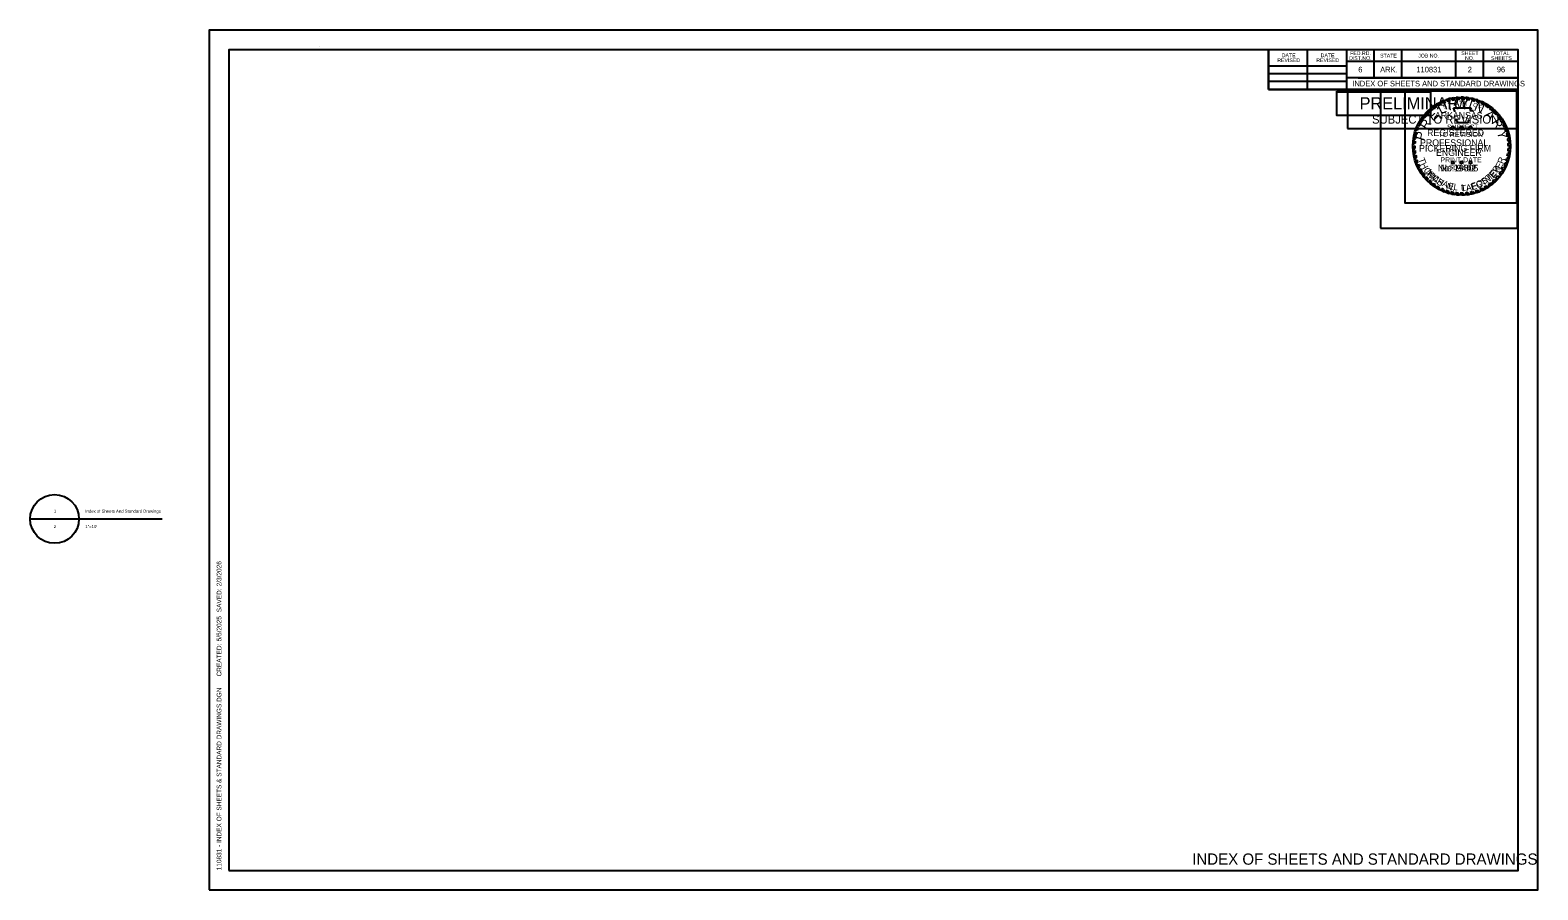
# Model space of a CAD drawing. Extents: x -0.19 to 1.42, y 0 to 0.92.
import ezdxf

# ---------------------------------------------------------------- set-up
doc = ezdxf.new("R2010")
doc.units = 0
for name, color, linetype in [('Default', 7, 'Continuous'), ('DSN_DRFT_Guideline-No-Plot', 7, 'Continuous'), ('SHET_Annotations', 7, 'Continuous'), ('SHET_Border-Lines', 7, 'Continuous'), ('SHET_Border-Text', 7, 'Continuous'), ('SHET_Stamp-Prelim', 7, 'Continuous'), ('SHET_Stamp-Seal', 7, 'Continuous'), ('STAMP_PE DIG SIG', 7, 'Continuous'), ('STAMP_PE_BACKGROUND', 7, 'Continuous'), ('STAMP_PE_FOSTER', 7, 'Continuous'), ('STAMP_PE_SEAL-INFO', 7, 'Continuous'), ('STAMP_PE_TAEGTMEYER', 7, 'Continuous'), ('STAMP_PRELIMINARY', 7, 'Continuous')]:
    doc.layers.add(name, color=color, linetype=linetype)

msp = doc.modelspace()

# ---------------------------------------------------------------- linework, layer by layer
at = {"layer": 'Default'}
for p, q in [((-0.191, 0.3955), (-0.1389, 0.3955)), ((-0.1647, 0.3955), (-0.0504, 0.3955))]:
    msp.add_line(p, q, dxfattribs=at)
msp.add_circle((-0.165, 0.3955), 0.026, dxfattribs=at)
at = {"layer": 'DSN_DRFT_Guideline-No-Plot'}
msp.add_lwpolyline([(0, 0), (1.4167, 0), (1.4167, 0.9167), (0, 0.9167)], close=True, dxfattribs=at)
at = {"layer": 'SHET_Border-Lines'}
for p, q in [((0.1176, 0.8988), (0.1176, 0.8988)), ((0.1176, 0.8988), (0.1176, 0.8988)), ((1.1296, 0.8534), (1.1296, 0.8958)), ((1.1711, 0.8534), (1.1711, 0.8958)), ((1.2127, 0.8958), (1.2127, 0.8534)), ((1.2417, 0.8958), (1.2417, 0.866)), ((1.2712, 0.8958), (1.2712, 0.866)), ((1.3289, 0.8958), (1.3289, 0.866)), ((1.3584, 0.8958), (1.3584, 0.866)), ((1.1296, 0.8786), (1.2127, 0.8786)), ((1.1296, 0.8706), (1.2127, 0.8706)), ((1.3958, 0.8832), (1.2127, 0.8832)), ((1.3958, 0.8833), (1.3958, 0.8833)), ((1.1296, 0.8622), (1.2127, 0.8622)), ((1.3958, 0.8534), (1.1296, 0.8534)), ((1.3958, 0.866), (1.2127, 0.866)), ((1.2252, 0.866), (1.3958, 0.866))]:
    msp.add_line(p, q, dxfattribs=at)
for points in [[(0.0208, 0.0208), (1.3958, 0.0208), (1.3958, 0.8958), (0.0208, 0.8958)], [(1.1296, 0.8534), (1.3958, 0.8534), (1.3958, 0.8958), (1.1296, 0.8958)]]:
    msp.add_lwpolyline(points, close=True, dxfattribs=at)
at = {"layer": 'SHET_Stamp-Prelim'}
msp.add_lwpolyline([(1.2137, 0.8119), (1.3948, 0.8119), (1.3948, 0.8524), (1.2137, 0.8524)], close=True, dxfattribs=at)
at = {"layer": 'SHET_Stamp-Seal'}
msp.add_line((1.3219, 0.7895), (1.3219, 0.7895), dxfattribs=at)
msp.add_lwpolyline([(1.249, 0.7057), (1.3948, 0.7057), (1.3948, 0.8524), (1.249, 0.8524)], close=True, dxfattribs=at)
at = {"layer": 'STAMP_PE DIG SIG'}
msp.add_lwpolyline([(1.2022, 0.8508), (1.3022, 0.8508), (1.3022, 0.8258), (1.2022, 0.8258)], close=True, dxfattribs=at)
at = {"layer": 'STAMP_PE_BACKGROUND'}
for points in [[(1.2022, 0.8517), (1.3022, 0.8517), (1.3022, 0.8258), (1.2022, 0.8258)], [(1.3942, 0.8517), (1.275, 0.8517), (1.275, 0.7325), (1.3942, 0.7325)]]:
    msp.add_lwpolyline(points, close=True, dxfattribs=at)
at = {"layer": 'STAMP_PE_SEAL-INFO'}
for p, q in [((1.3066, 0.8363), (1.309, 0.8352)), ((1.3087, 0.8377), (1.3112, 0.8365)), ((1.3112, 0.8391), (1.3138, 0.8378)), ((1.3137, 0.8403), (1.3158, 0.8387)), ((1.3165, 0.8415), (1.3181, 0.8397)), ((1.3184, 0.8422), (1.3206, 0.8405)), ((1.3217, 0.8432), (1.3233, 0.8413)), ((1.3239, 0.8438), (1.3259, 0.8418)), ((1.3266, 0.8443), (1.3283, 0.8422)), ((1.3295, 0.8447), (1.331, 0.8426)), ((1.3336, 0.8427), (1.3318, 0.8449)), ((1.3364, 0.8428), (1.3348, 0.845)), ((1.3389, 0.8426), (1.3375, 0.845)), ((1.3417, 0.8424), (1.3401, 0.8448)), ((1.3441, 0.842), (1.3427, 0.8445)), ((1.3473, 0.8413), (1.3463, 0.8439)), ((1.3495, 0.8407), (1.3486, 0.8433)), ((1.352, 0.8399), (1.3512, 0.8426)), ((1.3544, 0.839), (1.3536, 0.8418)), ((1.357, 0.8379), (1.3564, 0.8406)), ((1.3594, 0.8366), (1.359, 0.8394)), ((1.3616, 0.8353), (1.3614, 0.8381)), ((1.364, 0.8337), (1.3639, 0.8366)), ((1.2917, 0.8213), (1.2946, 0.8215)), ((1.293, 0.8232), (1.2959, 0.8232)), ((1.2946, 0.8253), (1.2977, 0.8254)), ((1.2965, 0.8276), (1.2994, 0.8274)), ((1.2983, 0.8295), (1.3014, 0.8293)), ((1.3002, 0.8313), (1.3028, 0.8306)), ((1.3021, 0.833), (1.3051, 0.8325)), ((1.3042, 0.8348), (1.3068, 0.8337)), ((1.3269, 0.8337), (1.3456, 0.8337)), ((1.3276, 0.832), (1.3269, 0.8337)), ((1.3281, 0.8303), (1.3276, 0.832)), ((1.3282, 0.8297), (1.3281, 0.8303)), ((1.3293, 0.8201), (1.3291, 0.8213)), ((1.331, 0.8201), (1.3293, 0.8201)), ((1.331, 0.8177), (1.331, 0.8201)), ((1.3429, 0.8213), (1.3424, 0.8196)), ((1.3456, 0.8337), (1.3443, 0.831)), ((1.3443, 0.831), (1.3478, 0.831)), ((1.3478, 0.831), (1.347, 0.8297)), ((1.366, 0.8322), (1.3662, 0.8349)), ((1.3685, 0.8301), (1.3687, 0.8331)), ((1.3703, 0.8285), (1.3707, 0.8313)), ((1.3723, 0.8264), (1.3727, 0.8294)), ((1.3738, 0.8247), (1.3746, 0.8273)), ((1.3756, 0.8223), (1.3764, 0.8251)), ((1.3769, 0.8206), (1.3779, 0.8232)), ((1.3786, 0.8178), (1.3796, 0.8205)), ((1.2847, 0.8048), (1.2873, 0.8059)), ((1.2853, 0.8071), (1.2879, 0.808)), ((1.2862, 0.8099), (1.2889, 0.8106)), ((1.287, 0.8121), (1.2898, 0.8129)), ((1.288, 0.8145), (1.2908, 0.8151)), ((1.2891, 0.8167), (1.2918, 0.8171)), ((1.2904, 0.8191), (1.2931, 0.8192)), ((1.3252, 0.8129), (1.3241, 0.8137)), ((1.3241, 0.8137), (1.3255, 0.8137)), ((1.3248, 0.8116), (1.3252, 0.8129)), ((1.3259, 0.8124), (1.3248, 0.8116)), ((1.3255, 0.8137), (1.3259, 0.815)), ((1.3259, 0.815), (1.3264, 0.8137)), ((1.327, 0.8116), (1.3259, 0.8124)), ((1.3264, 0.8137), (1.3277, 0.8137)), ((1.3277, 0.8137), (1.3266, 0.8129)), ((1.3266, 0.8129), (1.327, 0.8116)), ((1.3423, 0.8177), (1.331, 0.8177)), ((1.3347, 0.8129), (1.3336, 0.8137)), ((1.3336, 0.8137), (1.335, 0.8137)), ((1.3343, 0.8116), (1.3347, 0.8129)), ((1.3354, 0.8124), (1.3343, 0.8116)), ((1.335, 0.8137), (1.3354, 0.815)), ((1.3354, 0.815), (1.3358, 0.8137)), ((1.3365, 0.8116), (1.3354, 0.8124)), ((1.3358, 0.8137), (1.3372, 0.8137)), ((1.3372, 0.8137), (1.3361, 0.8129)), ((1.3361, 0.8129), (1.3365, 0.8116)), ((1.3424, 0.8196), (1.3423, 0.8177)), ((1.3442, 0.8129), (1.3431, 0.8137)), ((1.3431, 0.8137), (1.3445, 0.8137)), ((1.3438, 0.8116), (1.3442, 0.8129)), ((1.3449, 0.8124), (1.3438, 0.8116)), ((1.3445, 0.8137), (1.3449, 0.815)), ((1.3449, 0.815), (1.3453, 0.8137)), ((1.346, 0.8116), (1.3449, 0.8124)), ((1.3453, 0.8137), (1.3467, 0.8137)), ((1.3467, 0.8137), (1.3456, 0.8129)), ((1.3456, 0.8129), (1.346, 0.8116)), ((1.3797, 0.8157), (1.381, 0.8182)), ((1.381, 0.813), (1.3823, 0.8157)), ((1.3818, 0.8112), (1.3832, 0.8136)), ((1.3829, 0.8081), (1.3844, 0.8107)), ((1.3835, 0.8061), (1.3851, 0.8086)), ((1.3842, 0.8029), (1.386, 0.8054)), ((1.2857, 0.796), (1.2834, 0.7946)), ((1.2856, 0.7933), (1.2834, 0.7914)), ((1.2859, 0.7984), (1.2835, 0.7968)), ((1.2857, 0.791), (1.2835, 0.7892)), ((1.2862, 0.8008), (1.2838, 0.7996)), ((1.2858, 0.7882), (1.2838, 0.7862)), ((1.2867, 0.8034), (1.2841, 0.802)), ((1.3846, 0.8008), (1.3866, 0.8028)), ((1.3849, 0.7876), (1.3874, 0.7891)), ((1.385, 0.798), (1.387, 0.7998)), ((1.3851, 0.7956), (1.3873, 0.7973)), ((1.3852, 0.7927), (1.3875, 0.7945)), ((1.3852, 0.7905), (1.3875, 0.792)), ((1.2861, 0.7858), (1.2842, 0.7837)), ((1.2866, 0.7833), (1.2847, 0.7812)), ((1.2871, 0.7809), (1.2854, 0.7786)), ((1.2878, 0.7784), (1.2861, 0.7761)), ((1.2886, 0.7761), (1.287, 0.7738)), ((1.2895, 0.7737), (1.288, 0.7713)), ((1.3252, 0.7754), (1.3241, 0.7763)), ((1.3241, 0.7763), (1.3255, 0.7763)), ((1.3248, 0.7741), (1.3252, 0.7754)), ((1.3259, 0.7749), (1.3248, 0.7741)), ((1.3255, 0.7763), (1.3259, 0.7776)), ((1.3259, 0.7776), (1.3264, 0.7763)), ((1.327, 0.7741), (1.3259, 0.7749)), ((1.3264, 0.7763), (1.3277, 0.7763)), ((1.3277, 0.7763), (1.3266, 0.7754)), ((1.3266, 0.7754), (1.327, 0.7741)), ((1.3347, 0.7754), (1.3336, 0.7763)), ((1.3336, 0.7763), (1.335, 0.7763)), ((1.3343, 0.7741), (1.3347, 0.7754)), ((1.3354, 0.7749), (1.3343, 0.7741)), ((1.335, 0.7763), (1.3354, 0.7776)), ((1.3354, 0.7776), (1.3358, 0.7763)), ((1.3365, 0.7741), (1.3354, 0.7749)), ((1.3358, 0.7763), (1.3372, 0.7763)), ((1.3372, 0.7763), (1.3361, 0.7754)), ((1.3361, 0.7754), (1.3365, 0.7741)), ((1.3442, 0.7754), (1.3431, 0.7763)), ((1.3431, 0.7763), (1.3445, 0.7763)), ((1.3438, 0.7741), (1.3442, 0.7754)), ((1.3449, 0.7749), (1.3438, 0.7741)), ((1.3445, 0.7763), (1.3449, 0.7776)), ((1.3449, 0.7776), (1.3453, 0.7763)), ((1.346, 0.7741), (1.3449, 0.7749)), ((1.3453, 0.7763), (1.3467, 0.7763)), ((1.3467, 0.7763), (1.3456, 0.7754)), ((1.3456, 0.7754), (1.346, 0.7741)), ((1.3808, 0.7724), (1.3835, 0.7729)), ((1.382, 0.7753), (1.3847, 0.776)), ((1.3827, 0.7774), (1.3855, 0.7785)), ((1.3835, 0.7802), (1.3862, 0.7813)), ((1.3841, 0.7827), (1.3867, 0.7838)), ((1.3846, 0.7855), (1.3871, 0.7867)), ((1.2905, 0.7715), (1.2892, 0.769)), ((1.2918, 0.769), (1.2907, 0.7662)), ((1.2931, 0.7667), (1.2921, 0.7641)), ((1.2942, 0.765), (1.2936, 0.7619)), ((1.2958, 0.7628), (1.2952, 0.7598)), ((1.2975, 0.7607), (1.297, 0.7578)), ((1.2992, 0.7588), (1.2988, 0.7559)), ((1.301, 0.757), (1.3008, 0.754)), ((1.3702, 0.7573), (1.3727, 0.7566)), ((1.3716, 0.7588), (1.3743, 0.7583)), ((1.3738, 0.7612), (1.3763, 0.7608)), ((1.3755, 0.7634), (1.3783, 0.7634)), ((1.3774, 0.7662), (1.3801, 0.7661)), ((1.3783, 0.7677), (1.3811, 0.768)), ((1.3799, 0.7705), (1.3826, 0.7709)), ((1.3029, 0.7552), (1.3029, 0.7523)), ((1.3049, 0.7536), (1.305, 0.7507)), ((1.3068, 0.7522), (1.307, 0.7493)), ((1.3092, 0.7506), (1.3095, 0.7478)), ((1.3111, 0.7495), (1.3117, 0.7466)), ((1.3138, 0.7481), (1.3147, 0.7452)), ((1.3159, 0.7471), (1.3169, 0.7443)), ((1.3187, 0.7461), (1.3198, 0.7433)), ((1.321, 0.7453), (1.3222, 0.7426)), ((1.3238, 0.7445), (1.325, 0.7419)), ((1.326, 0.7441), (1.3274, 0.7415)), ((1.3288, 0.7436), (1.3302, 0.7411)), ((1.3313, 0.7433), (1.3328, 0.7409)), ((1.334, 0.7432), (1.3356, 0.7409)), ((1.3365, 0.7432), (1.3384, 0.741)), ((1.3394, 0.7433), (1.3412, 0.7412)), ((1.3419, 0.7436), (1.344, 0.7416)), ((1.3444, 0.744), (1.3465, 0.7421)), ((1.3471, 0.7446), (1.3492, 0.7427)), ((1.3497, 0.7453), (1.352, 0.7436)), ((1.3524, 0.7462), (1.3549, 0.7447)), ((1.3548, 0.7471), (1.3571, 0.7456)), ((1.3573, 0.7483), (1.36, 0.7471)), ((1.3596, 0.7494), (1.3619, 0.7481)), ((1.3619, 0.7508), (1.3644, 0.7497)), ((1.3639, 0.7521), (1.3663, 0.751)), ((1.3664, 0.754), (1.369, 0.7532)), ((1.3679, 0.7553), (1.3706, 0.7545))]:
    msp.add_line(p, q, dxfattribs=at)
for radius, start, end in [(0.0521, 123.6199, 126.5906), (0.0521, 117.6544, 120.8099), (0.0498, 115.6869, 119.1583), (0.0521, 111.3124, 114.7026), (0.0498, 110.3086, 113.1659), (0.0521, 105.2339, 109.0352), (0.0498, 104.0352, 107.3615), (0.0521, 99.7525, 102.7765), (0.0498, 98.258, 101.0329), (0.0521, 93.9381, 96.5517), (0.0498, 92.1102, 95.0367), (0.0521, 87.7298, 90.6707), (0.0498, 85.9628, 88.9097), (0.0521, 81.9732, 84.8236), (0.0498, 79.9264, 82.696), (0.0521, 75.3125, 77.9426), (0.0498, 73.5575, 76.2314), (0.0521, 69.6061, 72.3058), (0.0498, 67.6248, 70.504), (0.0521, 63.1329, 66.2704), (0.0498, 61.1558, 64.3784), (0.0521, 56.9003, 60.0942), (0.0521, 147.0072, 149.899), (0.0521, 141.6056, 144.4486), (0.0498, 145.0197, 148.2104), (0.0498, 139.301, 142.5873), (0.0521, 135.4021, 138.3031), (0.0498, 133.1331, 136.2562), (0.0521, 129.7326, 132.5376), (0.0498, 127.5297, 130.9683), (0.0498, 121.9746, 125.11), (0.0498, 54.9238, 58.2702), (0.0498, 48.3016, 52.0395), (0.0521, 50.3492, 53.7159), (0.0498, 42.2212, 45.5512), (0.0521, 44.3405, 47.3929), (0.0498, 36.135, 39.5311), (0.0521, 38.1247, 41.2316), (0.0498, 29.9032, 33.6645), (0.0521, 31.9614, 35.4294), (0.0521, 164.3068, 166.894), (0.0521, 158.4077, 161.0701), (0.0498, 162.4331, 165.0013), (0.0521, 152.864, 155.5189), (0.0498, 156.3402, 159.2319), (0.0498, 151.0315, 153.573), (0.0498, 23.7732, 27.2211), (0.0521, 25.9391, 29.0125), (0.0498, 17.6802, 21.4251), (0.0521, 19.9538, 23.3141), (0.0498, 11.5444, 15.2364), (0.0521, 13.8421, 17.4447), (0.0521, 175.7409, 178.2066), (0.0521, 181.7251, 184.1626), (0.0521, 170.0003, 172.6878), (0.0498, 179.6454, 182.2633), (0.0498, 173.73, 176.4734), (0.0498, 185.4539, 188.234), (0.0498, 167.9048, 170.9039), (0.0498, 5.7599, 9.0606), (0.0498, 353.8632, 357.1274), (0.0498, 359.7329, 3.0639), (0.0521, 7.5852, 10.8621), (0.0521, 1.7215, 4.7268), (0.0521, 355.7156, 358.9569), (0.0521, 187.4204, 190.1927), (0.0521, 193.0369, 195.9973), (0.0521, 198.8967, 201.6281), (0.0498, 191.2274, 193.9858), (0.0498, 196.9675, 199.8353), (0.0498, 202.7761, 205.4791), (0.0498, 335.6038, 339.1858), (0.0498, 341.777, 345.0925), (0.0521, 337.3837, 340.9933), (0.0498, 348.0778, 351.3435), (0.0521, 343.8925, 347.035), (0.0521, 349.8305, 353.0885), (0.0521, 204.5479, 207.4328), (0.0521, 210.8636, 213.6571), (0.0498, 208.7883, 211.7934), (0.0521, 216.6115, 219.491), (0.0498, 214.1838, 217.2747), (0.0521, 222.48, 225.3801), (0.0498, 220.3909, 223.3056), (0.0498, 226.2494, 229.2407), (0.0498, 310.7744, 314.3161), (0.0521, 312.4518, 315.6633), (0.0498, 316.6531, 320.3711), (0.0521, 318.2846, 321.8043), (0.0498, 323.5851, 327.4407), (0.0498, 329.5549, 333.2076), (0.0521, 325.4405, 328.9872), (0.0521, 331.4037, 334.9332), (0.0521, 228.3665, 231.348), (0.0498, 232.229, 234.9336), (0.0521, 234.295, 236.9452), (0.0498, 238.2223, 240.8353), (0.0521, 240.1977, 242.8613), (0.0498, 244.3204, 246.9486), (0.0521, 246.576, 249.1558), (0.0498, 250.3491, 253.1216), (0.0521, 252.5967, 255.3252), (0.0498, 256.505, 259.1192), (0.0521, 258.4433, 261.1398), (0.0498, 262.3783, 265.2012), (0.0521, 264.1978, 267.1009), (0.0498, 268.3215, 271.277), (0.0521, 270.2548, 273.3361), (0.0498, 274.6157, 277.4486), (0.0521, 276.4239, 279.4357), (0.0498, 280.3459, 283.5814), (0.0521, 282.3199, 285.3702), (0.0498, 286.6423, 289.9783), (0.0521, 288.5709, 291.9733), (0.0498, 292.8745, 296.1185), (0.0521, 294.6481, 298.2166), (0.0498, 299.0768, 302.1724), (0.0521, 300.621, 303.8703), (0.0498, 304.823, 308.5143), (0.0521, 306.3721, 310.208)]:
    msp.add_arc((1.3354, 0.793), radius, start, end, dxfattribs=at)
at = {"layer": 'STAMP_PRELIMINARY'}
msp.add_circle((1.3354, 0.793), 0.0521, dxfattribs=at)

# ---------------------------------------------------------------- texts
at = {"layer": 'Default'}
for s, height, p in [('1', 0.00328, (-0.1658, 0.4021)), ('Index of Sheets And Standard Drawings', 0.003281, (-0.1322, 0.4021)), ('2', 0.00328, (-0.1659, 0.3857)), ('1"=10\'', 0.00328, (-0.1322, 0.3857))]:
    msp.add_text(s, height=height, dxfattribs=at).set_placement(p)
at = {"layer": 'SHET_Annotations'}
for s, height, p in [('6', 0.006, (1.2252, 0.8716)), ('ARK.', 0.006, (1.2485, 0.8716)), ('110831', 0.006, (1.2871, 0.8716)), ('2', 0.006, (1.3419, 0.8716)), ('96', 0.006, (1.3729, 0.8717)), ('INDEX OF SHEETS AND STANDARD DRAWINGS', 0.006, (1.2188, 0.8567)), ('INDEX OF SHEETS AND STANDARD DRAWINGS', 0.012, (1.0481, 0.0268))]:
    msp.add_text(s, height=height, dxfattribs=at).set_placement(p)
at = {"layer": 'SHET_Border-Text'}
for s, p in [('REVISED', (1.1388, 0.8826)), ('DATE', (1.1436, 0.8878)), ('REVISED', (1.1804, 0.8826)), ('DATE', (1.1851, 0.8878)), ('DIST.NO.', (1.2154, 0.8849)), ('FED.RD.', (1.2165, 0.8901)), ('STATE', (1.2485, 0.8875)), ('JOB NO.', (1.2891, 0.8875)), ('SHEET', (1.335, 0.8901)), ('NO.', (1.339, 0.8849)), ('SHEETS', (1.3668, 0.8849)), ('TOTAL', (1.3686, 0.8901))]:
    msp.add_text(s, height=0.004, dxfattribs=at).set_placement(p)
for s, p in [('2/3/2026', (0.0129, 0.3236)), ('  SAVED: ', (0.0129, 0.2922)), ('5/5/2025', (0.0129, 0.265)), ('     CREATED: ', (0.0129, 0.218)), ('110831 - INDEX OF SHEETS & STANDARD DRAWINGS.DGN', (0.0129, 0.0208))]:
    msp.add_text(s, height=0.005, rotation=90, dxfattribs=at).set_placement(p)
at = {"layer": 'SHET_Stamp-Prelim'}
for s, height, p in [('PRELIMINARY', 0.013, (1.2266, 0.8322)), ('SUBJECT TO REVISION', 0.009, (1.2398, 0.817))]:
    msp.add_text(s, height=height, dxfattribs=at).set_placement(p)
at = {"layer": 'STAMP_PE_FOSTER'}
msp.add_text('No. 9402', height=0.00698, dxfattribs=at).set_placement((1.313, 0.7661))
for s, rotation, p in [('R', 54.5031, (1.373, 0.764)), ('M', 308.339, (1.297, 0.7652)), ('I', 314.1842, (1.3014, 0.7599)), ('C', 319.8733, (1.3034, 0.7579)), ('H', 327.7235, (1.3086, 0.7538)), ('A', 335.7276, (1.3141, 0.7506)), ('O', 23.719, (1.3526, 0.7487)), ('S', 31.7234, (1.3588, 0.7517)), ('T', 39.4194, (1.3641, 0.7552)), ('E', 46.9613, (1.3689, 0.7594)), ('E', 343.5779, (1.3204, 0.748)), ('L', 350.8115, (1.3263, 0.7464)), ('L', 1.2666, (1.3349, 0.7455)), ('.', 6.8035, (1.3408, 0.7459)), ('F', 15.8691, (1.3468, 0.7469))]:
    msp.add_text(s, height=0.0067, rotation=rotation, dxfattribs=at).set_placement(p)
at = {"layer": 'STAMP_PE_SEAL-INFO'}
for s, rotation, p in [('S', 23.5541, (1.3164, 0.8327)), ('T', 16.311, (1.3216, 0.8347)), ('A', 9.0679, (1.3269, 0.8361)), ('T', 1.8248, (1.3325, 0.8369)), ('E', 355.2002, (1.3375, 0.8369)), ('O', 342.2506, (1.3472, 0.8354)), ('F', 335.0075, (1.3526, 0.8335))]:
    msp.add_text(s, height=0.00436, rotation=rotation, dxfattribs=at).set_placement(p)
for s, height, p in [('ARKANSAS', 0.00698, (1.3069, 0.8223)), ('REGISTERED', 0.00698, (1.2986, 0.8038)), ('PROFESSIONAL', 0.006983, (1.2911, 0.7932)), ('ENGINEER', 0.00698, (1.3081, 0.7826))]:
    msp.add_text(s, height=height, dxfattribs=at).set_placement(p)
at = {"layer": 'STAMP_PE_TAEGTMEYER'}
for s, rotation, p in [('T', 289.646, (1.289, 0.7791)), ('H', 296.7339, (1.291, 0.7736)), ('Y', 53.9986, (1.3733, 0.7628)), ('E', 63.0984, (1.377, 0.768)), ('R', 69.57, (1.3798, 0.7735)), ('O', 303.7708, (1.2943, 0.7674)), ('M', 314.2033, (1.298, 0.7621)), ('A', 321.0594, (1.3034, 0.7567)), ('S', 327.8239, (1.308, 0.7531)), ('G', 23.3052, (1.3522, 0.7475)), ('T', 31.466, (1.3583, 0.7503)), ('M', 39.3, (1.3633, 0.7533)), ('E', 46.8094, (1.3692, 0.7582)), ('N', 344.2727, (1.3186, 0.7474)), ('.', 350.6464, (1.3254, 0.7456)), ('T', 3.0061, (1.3347, 0.7445)), ('A', 8.9826, (1.3405, 0.7448)), ('E', 17.6836, (1.3463, 0.7457))]:
    msp.add_text(s, height=0.00698, rotation=rotation, dxfattribs=at).set_placement(p)
msp.add_text('No. 19605', height=0.00698, dxfattribs=at).set_placement((1.3101, 0.7661))
at = {"layer": 'STAMP_PRELIMINARY'}
for s, rotation, p in [('L', 25.513, (1.3131, 0.8266)), ('I', 12.5248, (1.3217, 0.8309)), ('M', 3.1074, (1.3278, 0.8326)), ('I', 342.3164, (1.3416, 0.833)), ('N', 333.9382, (1.3478, 0.8315)), ('R', 56.2292, (1.2984, 0.8095)), ('E', 42.3578, (1.3048, 0.8192)), ('A', 315.6579, (1.3591, 0.8257)), ('R', 301.3831, (1.3668, 0.8184)), ('P', 73.913, (1.2953, 0.7982)), ('Y', 283.2593, (1.3729, 0.8084))]:
    msp.add_text(s, height=0.0101, rotation=rotation, dxfattribs=at).set_placement(p)
for s, height, p in [('TO REVISION', 0.005363, (1.3105, 0.8028)), ('SUBJECT', 0.00536, (1.3198, 0.8106)), ('PICKERING FIRM', 0.006983, (1.29, 0.7872)), ('PRINT DATE', 0.00536, (1.3128, 0.7757)), ('$DATE$', 0.00536, (1.3222, 0.768))]:
    msp.add_text(s, height=height, dxfattribs=at).set_placement(p)

doc.saveas('drawing.dxf')
